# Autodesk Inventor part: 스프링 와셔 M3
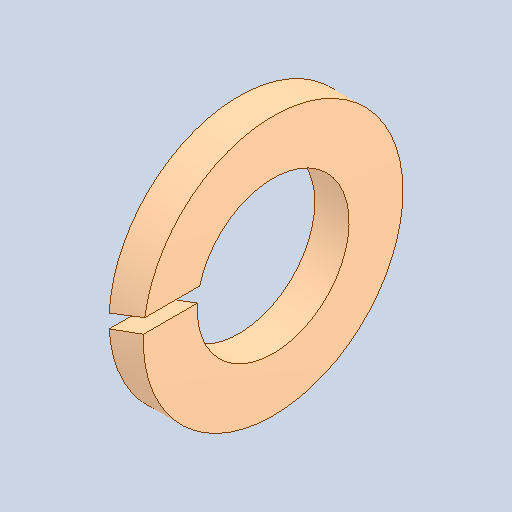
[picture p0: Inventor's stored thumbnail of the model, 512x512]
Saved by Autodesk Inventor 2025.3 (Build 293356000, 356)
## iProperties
Created: 2025-09
Part Number: 스프링 와셔 M3
Material: 강철, 연강
Description: 스프링 잠금 와셔
Document SubType Name: Modeling
Designer: PC-15
Density: 7.85 g/cm^3
Appearance: 기본값
Author: jhkim
Sending System: Autodesk Inventor 2026
Preprocessor: ST-DEVELOPER v20.1
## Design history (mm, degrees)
feature "Solid1"
node "솔리드1"
